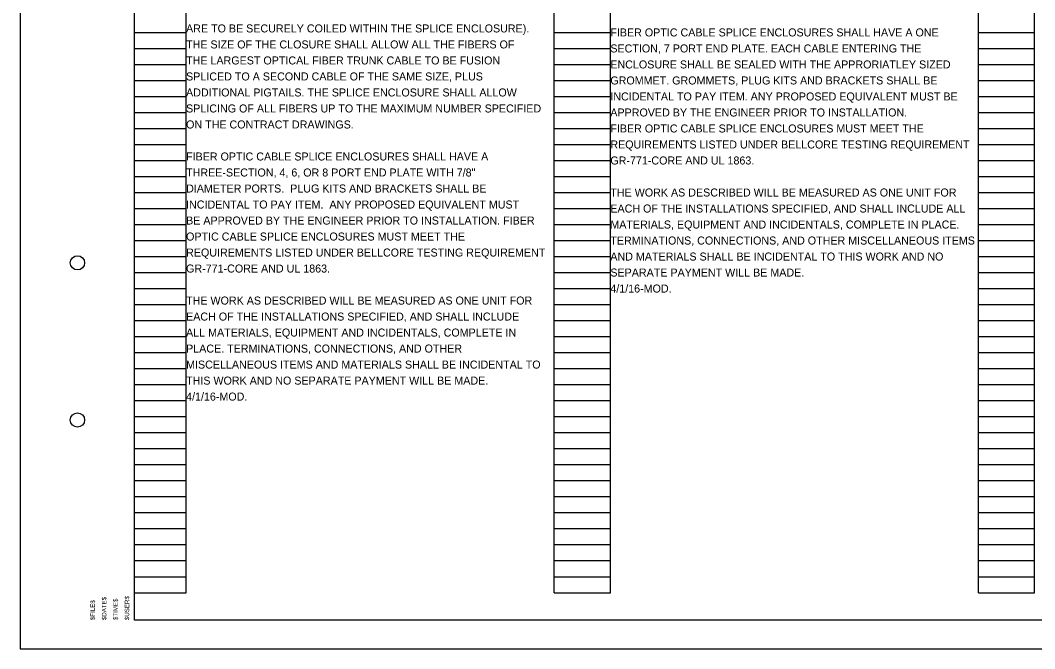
# Model space of a CAD drawing. Extents: x -39 to 75, y -25 to 14.
# Drawn here: x -0.51 to 17.24, y -7.51 to 3.48 of the extents above; entities that cross this region are included whole.
import ezdxf

# ---------------------------------------------------------------- set-up
doc = ezdxf.new("R2010")
doc.units = 0
for name, color, linetype in [('PF_P_Text', 7, 'Continuous'), ('SC_Scratch1', 7, 'Continuous'), ('SH_Cut_Line', 7, 'Continuous'), ('SH_Data', 7, 'Continuous'), ('SH_Text', 7, 'Continuous'), ('TX_P_Misc', 7, 'Continuous')]:
    doc.layers.add(name, color=color, linetype=linetype)

msp = doc.modelspace()

# ---------------------------------------------------------------- linework, layer by layer
at = {"layer": 'PF_P_Text'}
msp.add_lwpolyline([(1.494, 13.992), (32.994, 13.992), (32.994, -7.008), (1.494, -7.008)], close=True, dxfattribs=at)
for centre in [(0.494, -0.758), (0.494, -3.508)]:
    msp.add_circle(centre, 0.125, dxfattribs=at)
at = {"layer": 'SC_Scratch1'}
for p, q in [((1.494, -6.528), (1.494, 13.632)), ((2.394, -6.528), (2.394, 13.632)), ((8.834, -6.528), (8.834, 13.632)), ((9.814, -6.528), (9.814, 13.632)), ((16.254, -6.528), (16.254, 13.632)), ((17.234, -6.528), (17.234, 13.632)), ((1.494, 3.272), (2.394, 3.272)), ((8.834, 3.272), (9.814, 3.272)), ((16.254, 3.272), (17.234, 3.272)), ((1.494, 2.992), (2.394, 2.992)), ((8.834, 2.992), (9.814, 2.992)), ((16.254, 2.992), (17.234, 2.992)), ((1.494, 2.712), (2.394, 2.712)), ((8.834, 2.712), (9.814, 2.712)), ((16.254, 2.712), (17.234, 2.712)), ((1.494, 2.432), (2.394, 2.432)), ((8.834, 2.432), (9.814, 2.432)), ((16.254, 2.432), (17.234, 2.432)), ((1.494, 2.152), (2.394, 2.152)), ((8.834, 2.152), (9.814, 2.152)), ((16.254, 2.152), (17.234, 2.152)), ((1.494, 1.872), (2.394, 1.872)), ((8.834, 1.872), (9.814, 1.872)), ((16.254, 1.872), (17.234, 1.872)), ((1.494, 1.592), (2.394, 1.592)), ((8.834, 1.592), (9.814, 1.592)), ((16.254, 1.592), (17.234, 1.592)), ((1.494, 1.312), (2.394, 1.312)), ((8.834, 1.312), (9.814, 1.312)), ((16.254, 1.312), (17.234, 1.312)), ((1.494, 1.032), (2.394, 1.032)), ((8.834, 1.032), (9.814, 1.032)), ((16.254, 1.032), (17.234, 1.032)), ((1.494, 0.752), (2.394, 0.752)), ((8.834, 0.752), (9.814, 0.752)), ((16.254, 0.752), (17.234, 0.752)), ((1.494, 0.472), (2.394, 0.472)), ((8.834, 0.472), (9.814, 0.472)), ((16.254, 0.472), (17.234, 0.472)), ((1.494, 0.192), (2.394, 0.192)), ((8.834, 0.192), (9.814, 0.192)), ((16.254, 0.192), (17.234, 0.192)), ((1.494, -0.088), (2.394, -0.088)), ((8.834, -0.088), (9.814, -0.088)), ((16.254, -0.088), (17.234, -0.088)), ((1.494, -0.368), (2.394, -0.368)), ((8.834, -0.368), (9.814, -0.368)), ((16.254, -0.368), (17.234, -0.368)), ((1.494, -0.648), (2.394, -0.648)), ((8.834, -0.648), (9.814, -0.648)), ((16.254, -0.648), (17.234, -0.648)), ((1.494, -0.928), (2.394, -0.928)), ((8.834, -0.928), (9.814, -0.928)), ((16.254, -0.928), (17.234, -0.928)), ((1.494, -1.208), (2.394, -1.208)), ((8.834, -1.208), (9.814, -1.208)), ((16.254, -1.208), (17.234, -1.208)), ((1.494, -1.488), (2.394, -1.488)), ((8.834, -1.488), (9.814, -1.488)), ((16.254, -1.488), (17.234, -1.488)), ((1.494, -1.768), (2.394, -1.768)), ((8.834, -1.768), (9.814, -1.768)), ((16.254, -1.768), (17.234, -1.768)), ((1.494, -2.048), (2.394, -2.048)), ((8.834, -2.048), (9.814, -2.048)), ((16.254, -2.048), (17.234, -2.048)), ((1.494, -2.328), (2.394, -2.328)), ((8.834, -2.328), (9.814, -2.328)), ((16.254, -2.328), (17.234, -2.328)), ((1.494, -2.608), (2.394, -2.608)), ((8.834, -2.608), (9.814, -2.608)), ((16.254, -2.608), (17.234, -2.608)), ((1.494, -2.888), (2.394, -2.888)), ((8.834, -2.888), (9.814, -2.888)), ((16.254, -2.888), (17.234, -2.888)), ((1.494, -3.168), (2.394, -3.168)), ((8.834, -3.168), (9.814, -3.168)), ((16.254, -3.168), (17.234, -3.168)), ((1.494, -3.448), (2.394, -3.448)), ((8.834, -3.448), (9.814, -3.448)), ((16.254, -3.448), (17.234, -3.448)), ((1.494, -3.728), (2.394, -3.728)), ((8.834, -3.728), (9.814, -3.728)), ((16.254, -3.728), (17.234, -3.728)), ((1.494, -4.008), (2.394, -4.008)), ((8.834, -4.008), (9.814, -4.008)), ((16.254, -4.008), (17.234, -4.008)), ((1.494, -4.288), (2.394, -4.288)), ((8.834, -4.288), (9.814, -4.288)), ((16.254, -4.288), (17.234, -4.288)), ((1.494, -4.568), (2.394, -4.568)), ((8.834, -4.568), (9.814, -4.568)), ((16.254, -4.568), (17.234, -4.568)), ((1.494, -4.848), (2.394, -4.848)), ((8.834, -4.848), (9.814, -4.848)), ((16.254, -4.848), (17.234, -4.848)), ((1.494, -5.128), (2.394, -5.128)), ((8.834, -5.128), (9.814, -5.128)), ((16.254, -5.128), (17.234, -5.128)), ((1.494, -5.408), (2.394, -5.408)), ((8.834, -5.408), (9.814, -5.408)), ((16.254, -5.408), (17.234, -5.408)), ((1.494, -5.688), (2.394, -5.688)), ((8.834, -5.688), (9.814, -5.688)), ((16.254, -5.688), (17.234, -5.688)), ((1.494, -5.968), (2.394, -5.968)), ((8.834, -5.968), (9.814, -5.968)), ((16.254, -5.968), (17.234, -5.968)), ((1.494, -6.248), (2.394, -6.248)), ((8.834, -6.248), (9.814, -6.248)), ((16.254, -6.248), (17.234, -6.248)), ((1.494, -6.528), (2.394, -6.528)), ((8.834, -6.528), (9.814, -6.528)), ((16.254, -6.528), (17.234, -6.528)), ((-0.506, -7.508), (-0.506, -7.508))]:
    msp.add_line(p, q, dxfattribs=at)
at = {"layer": 'SH_Cut_Line'}
msp.add_lwpolyline([(-0.506, -7.508), (33.494, -7.508), (33.494, 14.492), (-0.506, 14.492)], close=True, dxfattribs=at)

# ---------------------------------------------------------------- texts
at = {"layer": 'SH_Data'}
for s, p in [('FIBER OPTIC CABLE SPLICE ENCLOSURES SHALL HAVE A ONE ', (9.814, 3.202)), ('SECTION, 7 PORT END PLATE. EACH CABLE ENTERING THE ', (9.814, 2.922)), ('ENCLOSURE SHALL BE SEALED WITH THE APPRORIATLEY SIZED ', (9.814, 2.642)), ('GROMMET. GROMMETS, PLUG KITS AND BRACKETS SHALL BE ', (9.814, 2.362)), ('INCIDENTAL TO PAY ITEM. ANY PROPOSED EQUIVALENT MUST BE ', (9.814, 2.082)), ('APPROVED BY THE ENGINEER PRIOR TO INSTALLATION. ', (9.814, 1.802)), ('FIBER OPTIC CABLE SPLICE ENCLOSURES MUST MEET THE ', (9.814, 1.522)), ('REQUIREMENTS LISTED UNDER BELLCORE TESTING REQUIREMENT ', (9.814, 1.242)), ('GR-771-CORE AND UL 1863.', (9.814, 0.962)), ('THE WORK AS DESCRIBED WILL BE MEASURED AS ONE UNIT FOR ', (9.814, 0.402)), ('EACH OF THE INSTALLATIONS SPECIFIED, AND SHALL INCLUDE ALL ', (9.814, 0.122)), ('MATERIALS, EQUIPMENT AND INCIDENTALS, COMPLETE IN PLACE. ', (9.814, -0.158)), ('TERMINATIONS, CONNECTIONS, AND OTHER MISCELLANEOUS ITEMS ', (9.814, -0.438)), ('AND MATERIALS SHALL BE INCIDENTAL TO THIS WORK AND NO ', (9.814, -0.718)), ('SEPARATE PAYMENT WILL BE MADE.', (9.814, -0.998)), ('4/1/16-MOD.', (9.814, -1.278))]:
    msp.add_text(s, height=0.14, dxfattribs=at).set_placement(p)
at = {"layer": 'SH_Text'}
for s, p in [('ARE TO BE SECURELY COILED WITHIN THE SPLICE ENCLOSURE).  ', (2.394, 3.272)), ('THE SIZE OF THE CLOSURE SHALL ALLOW ALL THE FIBERS OF ', (2.394, 2.992)), ('THE LARGEST OPTICAL FIBER TRUNK CABLE TO BE FUSION ', (2.394, 2.712)), ('SPLICED TO A SECOND CABLE OF THE SAME SIZE, PLUS ', (2.394, 2.432)), ('ADDITIONAL PIGTAILS. THE SPLICE ENCLOSURE SHALL ALLOW ', (2.394, 2.152)), ('SPLICING OF ALL FIBERS UP TO THE MAXIMUM NUMBER SPECIFIED ', (2.394, 1.872)), ('ON THE CONTRACT DRAWINGS.', (2.394, 1.592)), ('FIBER OPTIC CABLE SPLICE ENCLOSURES SHALL HAVE A ', (2.394, 1.032)), ('THREE-SECTION, 4, 6, OR 8 PORT END PLATE WITH 7/8" ', (2.394, 0.752)), ('DIAMETER PORTS.  PLUG KITS AND BRACKETS SHALL BE ', (2.394, 0.472)), ('INCIDENTAL TO PAY ITEM.  ANY PROPOSED EQUIVALENT MUST ', (2.394, 0.192)), ('BE APPROVED BY THE ENGINEER PRIOR TO INSTALLATION. FIBER ', (2.394, -0.088)), ('OPTIC CABLE SPLICE ENCLOSURES MUST MEET THE ', (2.394, -0.368)), ('REQUIREMENTS LISTED UNDER BELLCORE TESTING REQUIREMENT ', (2.394, -0.648)), ('GR-771-CORE AND UL 1863.', (2.394, -0.928)), ('THE WORK AS DESCRIBED WILL BE MEASURED AS ONE UNIT FOR ', (2.394, -1.488)), ('EACH OF THE INSTALLATIONS SPECIFIED, AND SHALL INCLUDE ', (2.394, -1.768)), ('ALL MATERIALS, EQUIPMENT AND INCIDENTALS, COMPLETE IN ', (2.394, -2.048)), ('PLACE. TERMINATIONS, CONNECTIONS, AND OTHER ', (2.394, -2.328)), ('MISCELLANEOUS ITEMS AND MATERIALS SHALL BE INCIDENTAL TO ', (2.394, -2.608)), ('THIS WORK AND NO SEPARATE PAYMENT WILL BE MADE.', (2.394, -2.888)), ('4/1/16-MOD.', (2.394, -3.168))]:
    msp.add_text(s, height=0.14, dxfattribs=at).set_placement(p)
at = {"layer": 'TX_P_Misc'}
for s, p in [('$FILE$', (0.799, -7.008)), ('$DATE$', (0.999, -7.008)), ('$TIME$', (1.199, -7.008)), ('$USER$', (1.399, -7.008))]:
    msp.add_text(s, height=0.078, rotation=90, dxfattribs=at).set_placement(p)

doc.saveas('drawing.dxf')
